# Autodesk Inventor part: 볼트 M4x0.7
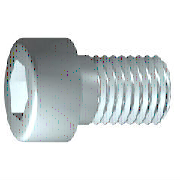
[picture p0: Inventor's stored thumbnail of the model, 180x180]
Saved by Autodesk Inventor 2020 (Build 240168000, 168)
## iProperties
Created: 2012-02
Part Number: 볼트 M4x0.7
Material: 스테인리스강
Description: 6각 소켓 머리 캡 나사
Document SubType Name: Modeling
Standard: ISO 4762
Designer: mduedu
Standard Revision: Fourth edition 2004-03-01
Standards Organization: ISO
Language: ko-KR
Size Designation: M4 x 12
Categories: <MemberInstance><Categories><Category DisplayName="조임쇠" InternalName="e4da775c-781d-43d5-af7c-5136215cf5a6" Mnemonic="FSTN"><Category DisplayName="볼트" InternalN
Density: 7.75 g/cm^3
Appearance: 반광택
IsCustomPart: 0
Author: mduedu
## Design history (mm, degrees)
sketch "스케치1"
  geometry: L1 (-1, 0)-(12, 0); L2 (12, 0)-(12, 2); L3 (12, 2)-(1.75, 2); L4 (1.75, 2)-(1.32, 2); L5 (1.32, 2)-(0, 2); L6 (0, 2)-(0, 3.5); L7 (0, 3.5)-(-4, 3.5); L8 (-4, 3.5)-(-4, 1.732); L9 (-4, 1.732)-(-2, 1.732); L10 (-2, 1.732)-(-1, 0); L11 (-7.2, 0)-(15.2, 0) reference; L12 (0, -0.7)-(0, 4.2) reference; L13 (1.75, 2)-(0, 2)
  constraints: 22 end point, 6 parallel, 2 collinear, 2 perpendicular, 1 horizontal, 1 point on line
  dimensions: "d1" = 10.25 distance from line of L3.end L2 (= GEL); "d2" = 0.42952 distance of L4.end L3.end (computed from GAL); "d3" = 4 distance between parallel lines of L8 L6 (= KOH); "d4" = 2 distance of L8.end L9.end (= INTI); "d5" = 60 deg angle of L10 L1; "d6" = 4 diameter of L3 L1 (= GD); "d7" = 4 diameter of L5 L1 (= BDM); "d8" = 3.4641 diameter of L9 L1 (= 1.1547 x SW); "d9" = 7 diameter of L7 L1 (= KOD); "d26" = 12 distance between parallel lines of L12 L2 (= NLG)
revolve "본체" sketch "스케치1" stored, may be unused: angle "d10" = 90 deg
sketch "스케치2"
  geometry: L1 (0, -4.9)-(0, 4.9) reference; L2 (-4.9, 0)-(4.9, 0) reference; L3 (1.732, 0)-(0.866, -1.5); L4 (0.866, -1.5)-(-0.866, -1.5); L5 (-0.866, -1.5)-(-1.732, 0); L6 (-1.732, 0)-(-0.866, 1.5); L7 (-0.866, 1.5)-(0.866, 1.5); L8 (0.866, 1.5)-(1.732, 0); 2 further points
  constraints: 12 end point, 1 coincident, 1 horizontal alignment, 1 point on line, 12 other
extrude "슬롯" join sketch "스케치2" stored distance "d11" = 10; taper "d12" = 0 deg
workplane "Work Plane1"
fillet "Fillet2" dims "d30" = 0.1 (= R)
body "Solid1"
fillet "모깎기1" dims "d17" = 0.4 (= RR)
feature "스레드" dims "d13" = 10.25 (= GEL), "d14" = 0
chamfer "모따기1" distance "d15" = 0.42941 (= -0.5 x SPD + 0.5 x GD); stored, may be unused: second distance "d16" = 0.42941 (= GUL), angle "d27" = 45 deg
other parameters: "GD" = 4 [user parameter; used in 2 equation terms], "NLG" = 12 [user parameter; used in 1 equation term], "GEL" = 10.25 [user parameter; used in 2 equation terms], "KOD" = 7 [user parameter; used in 1 equation term], "KOH" = 4 [user parameter; used in 1 equation term], "INTI" = 2 [user parameter; used in 1 equation term], "GAL" = 0.42941 (= 0.61345 x PTC) [user parameter; used in 1 equation term], "GUL" = 0.42941 (= 0.61345 x PTC) [user parameter; used in 1 equation term], "BDM" = 4 (= NND) [user parameter; used in 1 equation term], "SW" = 3 [user parameter; used in 2 equation terms], "RR" = 0.4 [user parameter; used in 1 equation term], "SPD" = 3.14117 (= NND - 1.2269 x PTC) [user parameter; used in 1 equation term], "d19" = 0, "d28" = 0, "d29" = 0, "R" = 0.1 [user parameter; used in 1 equation term], "TOA" = 30 deg [user parameter], "GD1" = 3.14117 (= THREADDIA - 1.2269 x PTC) [user parameter], "THREADDIA" = 4 [user parameter; used in 1 equation term], "FAWI" = 45 deg [user parameter], "TPU" = 14.28571 (computed from PTC) [user parameter], "PTC" = 0.7 [user parameter; used in 5 equation terms], "NND" = 4 [user parameter; used in 2 equation terms], "E0" = 3.465 (= 1.155 x SW) [user parameter]
